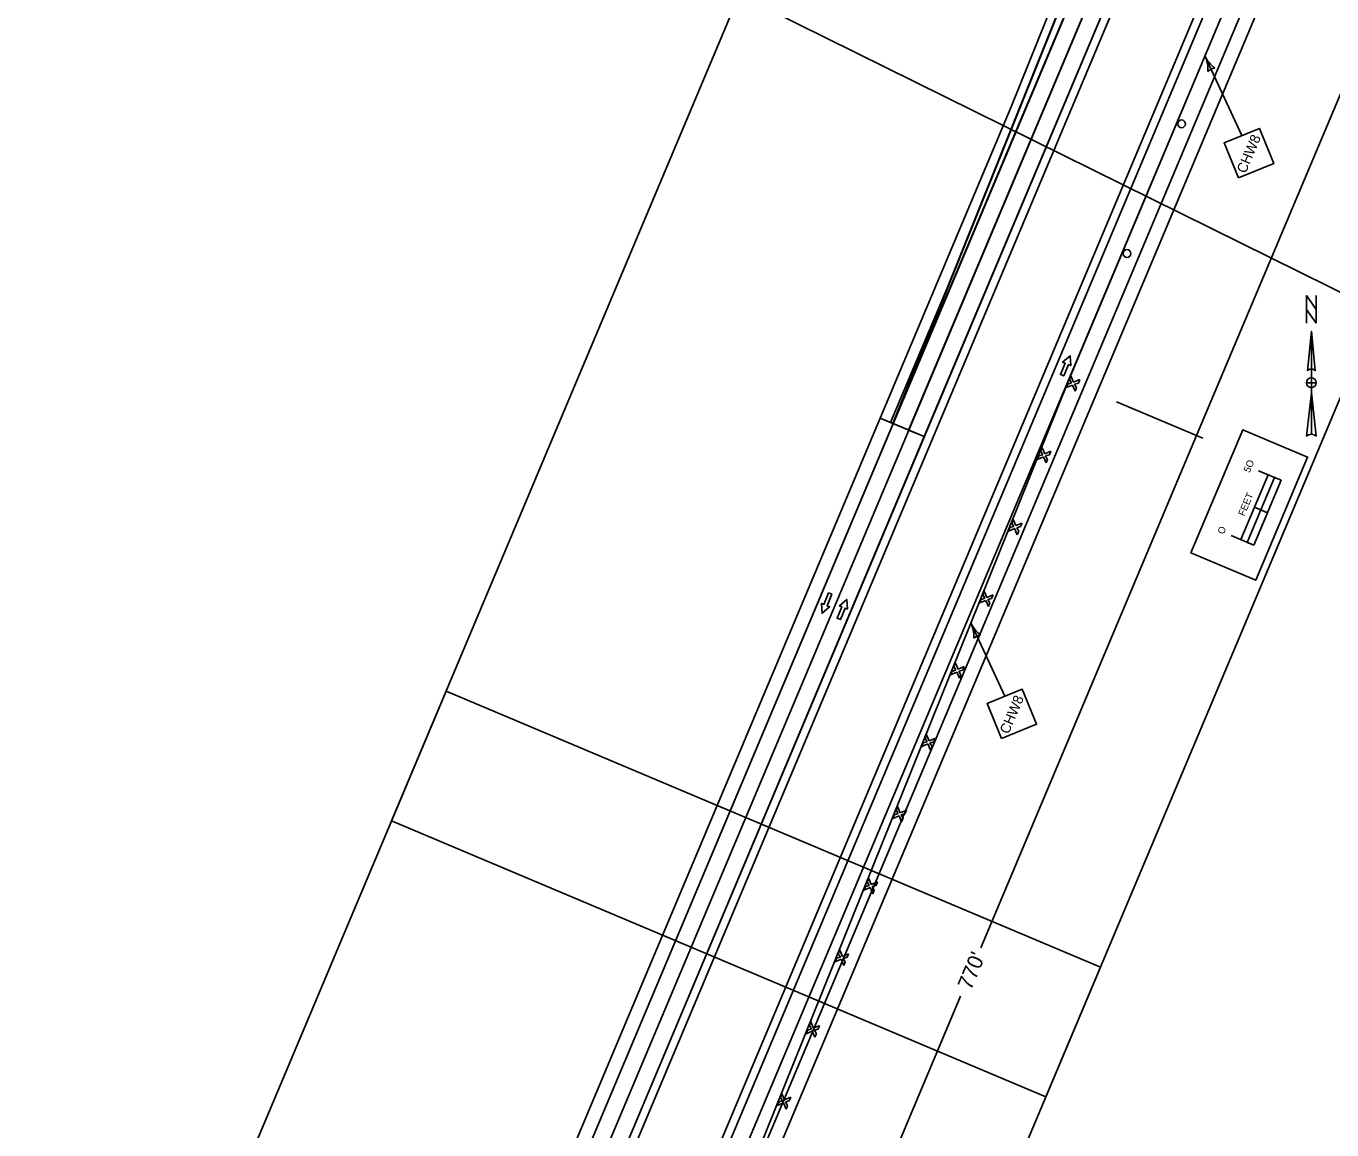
# Model space of a CAD drawing. Extents: x 14104283 to 14129344, y 8637090 to 8673339.
# Drawn here: x 14117797 to 14118725, y 8666942 to 8667727 of the extents above; entities that cross this region are included whole.
import ezdxf

# ---------------------------------------------------------------- set-up
doc = ezdxf.new("R2010")
doc.units = 0
for name, color, linetype in [('Cell', 7, 'Continuous'), ('Default', 7, 'Continuous'), ('dsnCellsNorthArrow', 7, 'Continuous'), ('dsnCellsScaleBlock', 7, 'Continuous'), ('dsnNonPlotable', 7, 'Continuous'), ('dsnPaintExistingBrokenLaneLineWhite', 7, 'Continuous'), ('dsnPaintExistingEdgeLineLeftYellow', 7, 'Continuous'), ('dsnPaintExistingEdgeLineRightWhite', 7, 'Continuous'), ('dsnPaintPlaceChannelizingLaneWhite', 7, 'Continuous'), ('dsnShadingPaved', 7, 'Continuous'), ('dsnStdLabel', 7, 'Continuous'), ('dsnStgShadingPrevPav', 7, 'Continuous'), ('dsnTapePlaceChannelizingLaneWhite', 7, 'Continuous')]:
    doc.layers.add(name, color=color, linetype=linetype)

msp = doc.modelspace()

# ---------------------------------------------------------------- linework, layer by layer
at = {"layer": 'Cell'}
for p, q in [((14118539.73, 8667478.12), (14118538.71, 8667475.57)), ((14118541.6, 8667473.73), (14118539.73, 8667478.12)), ((14118537.4, 8667472.32), (14118536.37, 8667469.77)), ((14118536.37, 8667469.77), (14118540.76, 8667471.64)), ((14118540.14, 8667473.1), (14118537.4, 8667472.32)), ((14118538.71, 8667475.57), (14118540.14, 8667473.1)), ((14118540.76, 8667471.64), (14118542.63, 8667467.25)), ((14118545.99, 8667475.6), (14118541.6, 8667473.73)), ((14118542.23, 8667472.26), (14118544.97, 8667473.04)), ((14118543.66, 8667469.8), (14118542.23, 8667472.26)), ((14118542.63, 8667467.25), (14118543.66, 8667469.8)), ((14118544.97, 8667473.04), (14118545.99, 8667475.6)), ((14118516.84, 8667421.31), (14118515.82, 8667418.75)), ((14118519.59, 8667422.09), (14118516.84, 8667421.31)), ((14118519.18, 8667427.1), (14118518.15, 8667424.55)), ((14118518.15, 8667424.55), (14118519.59, 8667422.09)), ((14118521.05, 8667422.71), (14118519.18, 8667427.1)), ((14118525.44, 8667424.58), (14118521.05, 8667422.71)), ((14118521.67, 8667421.25), (14118524.41, 8667422.03)), ((14118523.11, 8667418.78), (14118521.67, 8667421.25)), ((14118524.41, 8667422.03), (14118525.44, 8667424.58)), ((14118515.82, 8667418.75), (14118520.21, 8667420.62)), ((14118520.21, 8667420.62), (14118522.08, 8667416.23)), ((14118522.08, 8667416.23), (14118523.11, 8667418.78)), ((14118498.63, 8667376.09), (14118497.6, 8667373.54)), ((14118500.5, 8667371.7), (14118498.63, 8667376.09)), ((14118496.29, 8667370.29), (14118495.26, 8667367.74)), ((14118495.26, 8667367.74), (14118499.66, 8667369.61)), ((14118499.03, 8667371.07), (14118496.29, 8667370.29)), ((14118497.6, 8667373.54), (14118499.03, 8667371.07)), ((14118499.66, 8667369.61), (14118501.52, 8667365.22)), ((14118504.89, 8667373.56), (14118500.5, 8667371.7)), ((14118501.12, 8667370.23), (14118503.86, 8667371.01)), ((14118502.55, 8667367.77), (14118501.12, 8667370.23)), ((14118501.52, 8667365.22), (14118502.55, 8667367.77)), ((14118503.86, 8667371.01), (14118504.89, 8667373.56)), ((14118475.74, 8667319.27), (14118474.71, 8667316.72)), ((14118478.48, 8667320.06), (14118475.74, 8667319.27)), ((14118478.07, 8667325.07), (14118477.05, 8667322.52)), ((14118477.05, 8667322.52), (14118478.48, 8667320.06)), ((14118479.94, 8667320.68), (14118478.07, 8667325.07)), ((14118484.33, 8667322.55), (14118479.94, 8667320.68)), ((14118480.57, 8667319.22), (14118483.31, 8667320)), ((14118482, 8667316.75), (14118480.57, 8667319.22)), ((14118483.31, 8667320), (14118484.33, 8667322.55)), ((14118474.71, 8667316.72), (14118479.1, 8667318.59)), ((14118479.1, 8667318.59), (14118480.97, 8667314.2)), ((14118480.97, 8667314.2), (14118482, 8667316.75)), ((14118457.52, 8667274.06), (14118456.49, 8667271.51)), ((14118459.39, 8667269.66), (14118457.52, 8667274.06)), ((14118455.18, 8667268.26), (14118454.16, 8667265.71)), ((14118454.16, 8667265.71), (14118458.55, 8667267.58)), ((14118457.93, 8667269.04), (14118455.18, 8667268.26)), ((14118456.49, 8667271.51), (14118457.93, 8667269.04)), ((14118458.55, 8667267.58), (14118460.42, 8667263.19)), ((14118463.78, 8667271.53), (14118459.39, 8667269.66)), ((14118460.01, 8667268.2), (14118462.75, 8667268.98)), ((14118461.45, 8667265.74), (14118460.01, 8667268.2)), ((14118460.42, 8667263.19), (14118461.45, 8667265.74)), ((14118462.75, 8667268.98), (14118463.78, 8667271.53)), ((14118434.63, 8667217.24), (14118433.6, 8667214.69)), ((14118433.6, 8667214.69), (14118437.99, 8667216.56)), ((14118437.37, 8667218.03), (14118434.63, 8667217.24)), ((14118436.97, 8667223.04), (14118435.94, 8667220.49)), ((14118435.94, 8667220.49), (14118437.37, 8667218.03)), ((14118438.84, 8667218.65), (14118436.97, 8667223.04)), ((14118437.99, 8667216.56), (14118439.86, 8667212.17)), ((14118443.23, 8667220.52), (14118438.84, 8667218.65)), ((14118439.46, 8667217.19), (14118442.2, 8667217.97)), ((14118440.89, 8667214.72), (14118439.46, 8667217.19)), ((14118442.2, 8667217.97), (14118443.23, 8667220.52)), ((14118439.86, 8667212.17), (14118440.89, 8667214.72)), ((14118416.41, 8667172.03), (14118415.39, 8667169.48)), ((14118418.28, 8667167.63), (14118416.41, 8667172.03)), ((14118414.08, 8667166.23), (14118413.05, 8667163.68)), ((14118413.05, 8667163.68), (14118417.44, 8667165.55)), ((14118416.82, 8667167.01), (14118414.08, 8667166.23)), ((14118415.39, 8667169.48), (14118416.82, 8667167.01)), ((14118417.44, 8667165.55), (14118419.31, 8667161.16)), ((14118422.67, 8667169.5), (14118418.28, 8667167.63)), ((14118418.91, 8667166.17), (14118421.65, 8667166.95)), ((14118420.34, 8667163.71), (14118418.91, 8667166.17)), ((14118419.31, 8667161.16), (14118420.34, 8667163.71)), ((14118421.65, 8667166.95), (14118422.67, 8667169.5)), ((14118393.52, 8667115.21), (14118392.5, 8667112.66)), ((14118392.5, 8667112.66), (14118396.89, 8667114.53)), ((14118396.27, 8667116), (14118393.52, 8667115.21)), ((14118395.86, 8667121.01), (14118394.83, 8667118.46)), ((14118394.83, 8667118.46), (14118396.27, 8667116)), ((14118397.73, 8667116.62), (14118395.86, 8667121.01)), ((14118396.89, 8667114.53), (14118398.76, 8667110.14)), ((14118402.12, 8667118.49), (14118397.73, 8667116.62)), ((14118398.35, 8667115.16), (14118401.09, 8667115.94)), ((14118399.79, 8667112.69), (14118398.35, 8667115.16)), ((14118401.09, 8667115.94), (14118402.12, 8667118.49)), ((14118398.76, 8667110.14), (14118399.79, 8667112.69)), ((14118375.31, 8667070), (14118374.28, 8667067.44)), ((14118377.18, 8667065.6), (14118375.31, 8667070)), ((14118372.97, 8667064.2), (14118371.94, 8667061.65)), ((14118371.94, 8667061.65), (14118376.33, 8667063.52)), ((14118375.71, 8667064.98), (14118372.97, 8667064.2)), ((14118374.28, 8667067.44), (14118375.71, 8667064.98)), ((14118376.33, 8667063.52), (14118378.2, 8667059.13)), ((14118381.57, 8667067.47), (14118377.18, 8667065.6)), ((14118377.8, 8667064.14), (14118380.54, 8667064.92)), ((14118379.23, 8667061.68), (14118377.8, 8667064.14)), ((14118378.2, 8667059.13), (14118379.23, 8667061.68)), ((14118380.54, 8667064.92), (14118381.57, 8667067.47)), ((14118352.42, 8667013.18), (14118351.39, 8667010.63)), ((14118351.39, 8667010.63), (14118355.78, 8667012.5)), ((14118355.16, 8667013.97), (14118352.42, 8667013.18)), ((14118354.75, 8667018.98), (14118353.73, 8667016.43)), ((14118353.73, 8667016.43), (14118355.16, 8667013.97)), ((14118356.62, 8667014.59), (14118354.75, 8667018.98)), ((14118355.78, 8667012.5), (14118357.65, 8667008.11)), ((14118361.01, 8667016.46), (14118356.62, 8667014.59)), ((14118357.25, 8667013.12), (14118359.99, 8667013.91)), ((14118358.68, 8667010.66), (14118357.25, 8667013.12)), ((14118359.99, 8667013.91), (14118361.01, 8667016.46)), ((14118357.65, 8667008.11), (14118358.68, 8667010.66)), ((14118334.2, 8666967.96), (14118333.17, 8666965.41)), ((14118336.07, 8666963.57), (14118334.2, 8666967.96)), ((14118331.86, 8666962.17), (14118330.84, 8666959.62)), ((14118330.84, 8666959.62), (14118335.23, 8666961.49)), ((14118334.6, 8666962.95), (14118331.86, 8666962.17)), ((14118333.17, 8666965.41), (14118334.6, 8666962.95)), ((14118335.23, 8666961.49), (14118337.1, 8666957.09)), ((14118340.46, 8666965.44), (14118336.07, 8666963.57)), ((14118336.69, 8666962.11), (14118339.43, 8666962.89)), ((14118338.12, 8666959.65), (14118336.69, 8666962.11)), ((14118337.1, 8666957.09), (14118338.12, 8666959.65)), ((14118339.43, 8666962.89), (14118340.46, 8666965.44))]:
    msp.add_line(p, q, dxfattribs=at)
for points in [[(14118534.52, 8667478.07), (14118532.2, 8667479.01), (14118535.52, 8667487.11), (14118533.79, 8667487.82), (14118539.05, 8667492.42), (14118539.57, 8667485.45), (14118537.84, 8667486.16)], [(14118367.3, 8667323.84), (14118369.62, 8667322.89), (14118366.29, 8667314.79), (14118368.03, 8667314.08), (14118362.76, 8667309.49), (14118362.25, 8667316.45), (14118363.98, 8667315.74)], [(14118375.73, 8667304.96), (14118373.42, 8667305.91), (14118376.74, 8667314), (14118375, 8667314.71), (14118380.27, 8667319.31), (14118380.78, 8667312.34), (14118379.05, 8667313.05)]]:
    msp.add_lwpolyline(points, close=True, dxfattribs=at)
for points in [[(14118537.84, 8667486.16), (14118539.57, 8667485.45), (14118539.05, 8667492.42), (14118533.79, 8667487.82), (14118535.52, 8667487.11), (14118532.2, 8667479.01), (14118534.52, 8667478.07), (14118537.84, 8667486.16)], [(14118363.98, 8667315.74), (14118362.25, 8667316.45), (14118362.76, 8667309.49), (14118368.03, 8667314.08), (14118366.29, 8667314.79), (14118369.62, 8667322.89), (14118367.3, 8667323.84), (14118363.98, 8667315.74)], [(14118379.05, 8667313.05), (14118380.78, 8667312.34), (14118380.27, 8667319.31), (14118375, 8667314.71), (14118376.74, 8667314), (14118373.42, 8667305.91), (14118375.73, 8667304.96), (14118379.05, 8667313.05)]]:
    msp.add_lwpolyline(points, dxfattribs=at)
for centre in [(14118618.36, 8667657.23), (14118579.53, 8667565.07)]:
    msp.add_circle(centre, 2.75, dxfattribs=at)
at = {"layer": 'Default'}
msp.add_line((14118435.37, 8667434.94), (14118413.25, 8667444.25), dxfattribs=at)
for points in [[(14118413.25, 8667444.25), (14110818.39, 8649409.15), (14109142.61, 8645431.44)], [(14109164.73, 8645422.12), (14110840.51, 8649399.84), (14118435.37, 8667434.94)]]:
    msp.add_lwpolyline(points, dxfattribs=at)
at = {"layer": 'dsnCellsNorthArrow'}
for p, q in [((14118710.66, 8667509.85), (14118713.47, 8667481.68)), ((14118710.66, 8667509.85), (14118710.66, 8667436.61)), ((14118707.84, 8667481.68), (14118707.84, 8667481.68)), ((14118707.95, 8667481.94), (14118708.47, 8667482.53)), ((14118710.66, 8667469.71), (14118710.66, 8667469.71)), ((14118707.14, 8667435.2), (14118710.66, 8667466.19))]:
    msp.add_line(p, q, dxfattribs=at)
msp.add_lwpolyline([(14118714.18, 8667515.49), (14118707.14, 8667525.35), (14118707.14, 8667535.21), (14118714.18, 8667525.35)], close=True, dxfattribs=at)
for points in [[(14118707.14, 8667515.49), (14118707.14, 8667535.21), (14118714.18, 8667525.35), (14118714.18, 8667535.21)], [(14118707.84, 8667481.68), (14118710.66, 8667509.85), (14118710.66, 8667483.09)], [(14118714.18, 8667473.23), (14118710.66, 8667473.23), (14118710.66, 8667476.75)], [(14118710.66, 8667469.71), (14118710.66, 8667473.23), (14118707.14, 8667473.23)], [(14118710.66, 8667436.61), (14118710.66, 8667466.19), (14118714.18, 8667435.2)]]:
    msp.add_lwpolyline(points, dxfattribs=at)
for centre, radius, start, end in [((14118710.66, 8667473.23), 3.52, 90, 180), ((14118710.66, 8667479.57), 3.52, 90.02039, 143.12574), ((14118710.66, 8667479.57), 3.52, 36.84806, 90.02184), ((14118710.66, 8667473.23), 3.52, 0, 90), ((14118710.66, 8667473.23), 3.52, 180, 270), ((14118710.66, 8667473.23), 3.52, 270, 360), ((14118710.66, 8667431.51), 5.1, 89.98939, 133.61895), ((14118710.66, 8667431.5), 5.11, 46.40206, 90.00064)]:
    msp.add_arc(centre, radius, start, end, dxfattribs=at)
at = {"layer": 'dsnCellsScaleBlock'}
msp.add_line((14118679.37, 8667380.9), (14118670.15, 8667384.78), dxfattribs=at)
msp.add_line((14118679.37, 8667380.9), (14118670.15, 8667384.78), dxfattribs=at)
for points in [[(14118671.06, 8667332.86), (14118624.98, 8667352.27), (14118661.87, 8667439.82), (14118707.94, 8667420.4)], [(14118624.98, 8667352.27), (14118661.87, 8667439.82), (14118707.94, 8667420.4), (14118671.06, 8667332.86)], [(14118671.06, 8667332.86), (14118624.98, 8667352.27), (14118661.87, 8667439.82), (14118707.94, 8667420.4)], [(14118674.73, 8667382.85), (14118684.43, 8667405.89), (14118679.86, 8667407.82), (14118670.15, 8667384.78)], [(14118669.66, 8667357.86), (14118679.37, 8667380.9), (14118674.73, 8667382.85), (14118665.02, 8667359.82)]]:
    msp.add_lwpolyline(points, close=True, dxfattribs=at)
for points in [[(14118653.53, 8667364.66), (14118669.66, 8667357.86), (14118689.07, 8667403.94), (14118672.95, 8667410.73)], [(14118660.44, 8667361.74), (14118679.86, 8667407.82)]]:
    msp.add_lwpolyline(points, dxfattribs=at)
at = {"layer": 'dsnNonPlotable'}
for points in [[(14118092.03, 8667853.71), (14118786.76, 8669258.84), (14119692.14, 8668811.2), (14118997.41, 8667406.07)], [(14118056.48, 8667161.91), (14118665.06, 8668606.45), (14119130.44, 8668410.38), (14118521.87, 8666965.84)], [(14117486.73, 8665809.52), (14118095.31, 8667254.06), (14118560.69, 8667058), (14117952.12, 8665613.46)]]:
    msp.add_lwpolyline(points, close=True, dxfattribs=at)
at = {"layer": 'dsnPaintExistingBrokenLaneLineWhite'}
for p, q in [((14114932.53, 8658913.38), (14118863.73, 8668248.6)), ((14118664.08, 8668008.96), (14118424.31, 8667439.59)), ((14110829.45, 8649404.5), (14118424.31, 8667439.59))]:
    msp.add_line(p, q, dxfattribs=at)
at = {"layer": 'dsnPaintExistingEdgeLineLeftYellow'}
for p, q in [((14115900.95, 8661243.95), (14118759.37, 8668031.7)), ((14118675.14, 8668004.3), (14118435.37, 8667434.94)), ((14118435.37, 8667434.94), (14115816.14, 8661215.2)), ((14118435.37, 8667434.94), (14115816.14, 8661215.2))]:
    msp.add_line(p, q, dxfattribs=at)
at = {"layer": 'dsnPaintExistingEdgeLineRightWhite'}
for p, q in [((14110924.38, 8649364.51), (14118874.68, 8668243.67)), ((14118643.53, 8668017.62), (14118412.94, 8667444.38)), ((14118413.25, 8667444.25), (14115798.75, 8661235.75))]:
    msp.add_line(p, q, dxfattribs=at)
at = {"layer": 'dsnPaintPlaceChannelizingLaneWhite'}
msp.add_line((14118766.99, 8668018.87), (14118537.63, 8667474.22), dxfattribs=at)
at = {"layer": 'dsnShadingPaved'}
for p, q in [((14118227.72, 8666769.23), (14118759.37, 8668031.7)), ((14118770.49, 8668027.18), (14118537.63, 8667474.22)), ((14118534.18, 8667731.73), (14118412.93, 8667443.47)), ((14118412.93, 8667443.47), (14118528.39, 8667730.93)), ((14118537.63, 8667474.22), (14118249.84, 8666759.92))]:
    msp.add_line(p, q, dxfattribs=at)
for points in [[(14118653.02, 8668013.62), (14118412.94, 8667444.38), (14118424.31, 8667439.59), (14118664.08, 8668008.96)], [(14118435.37, 8667434.94), (14118675.14, 8668004.3), (14118664.08, 8668008.96), (14118424.15, 8667439.66)]]:
    msp.add_lwpolyline(points, close=True, dxfattribs=at)
at = {"layer": 'dsnStdLabel'}
for p, q in [((14118661.18, 8667648.87), (14118635.01, 8667705.48)), ((14118738.7, 8667695.95), (14118629.06, 8667435.71)), ((14118633.49, 8667433.84), (14118572.19, 8667459.66)), ((14118629.06, 8667435.71), (14118475.65, 8667071.56)), ((14118492.61, 8667250.42), (14118468.49, 8667302.61)), ((14118461.19, 8667037.24), (14118330.11, 8666726.11))]:
    msp.add_line(p, q, dxfattribs=at)
for points in [[(14118658.86, 8667618.77), (14118683.86, 8667628.95), (14118673.68, 8667653.96), (14118648.67, 8667643.78)], [(14118490.29, 8667220.32), (14118515.3, 8667230.5), (14118505.11, 8667255.51), (14118480.11, 8667245.32)]]:
    msp.add_lwpolyline(points, close=True, dxfattribs=at)
for centre, radius, start, end in [((14118614.18, 8667695.85), 22.95, 356.73394, 24.80525), ((14118655.85, 8667715.11), 22.95, 204.8051, 232.87636), ((14118643.09, 8667688.01), 8.86, 97.07093, 132.53937), ((14118447.66, 8667292.98), 22.95, 356.73394, 24.80525), ((14118489.32, 8667312.24), 22.95, 204.8051, 232.87636), ((14118476.56, 8667285.14), 8.86, 97.07093, 132.53937)]:
    msp.add_arc(centre, radius, start, end, dxfattribs=at)
at = {"layer": 'dsnStgShadingPrevPav'}
for p, q in [((14115895.65, 8661246.83), (14118811.53, 8668171.01)), ((14118848.39, 8668155.49), (14115932.51, 8661231.3)), ((14118457.98, 8667555.62), (14118643.53, 8668017.62)), ((14118457.98, 8667555.62), (14118643.53, 8668017.62)), ((14118637.96, 8668019.85), (14118497.16, 8667669.27)), ((14118653.02, 8668013.62), (14115794.02, 8661224.52)), ((14118652.65, 8668013.06), (14118415.89, 8667450.85)), ((14115816.14, 8661215.2), (14118675.14, 8668004.3)), ((14115816.14, 8661215.2), (14118675.14, 8668004.3)), ((14118680.66, 8668001.98), (14115821.67, 8661212.88)), ((14118497.16, 8667669.27), (14118404.03, 8667448.13)), ((14118411.4, 8667445.03), (14118457.98, 8667555.62)), ((14118411.4, 8667445.03), (14118457.98, 8667555.62)), ((14118415.89, 8667450.85), (14118413.13, 8667444.3)), ((14110809.18, 8649413.03), (14118404.03, 8667448.13)), ((14118413.25, 8667444.25), (14110818.39, 8649409.15)), ((14118404.03, 8667448.13), (14118411.4, 8667445.03)), ((14118404.03, 8667448.13), (14118413.25, 8667444.25)), ((14118413.25, 8667444.25), (14118411.4, 8667445.03))]:
    msp.add_line(p, q, dxfattribs=at)
at = {"layer": 'dsnTapePlaceChannelizingLaneWhite'}
msp.add_line((14118249.84, 8666759.92), (14118537.63, 8667474.22), dxfattribs=at)

# ---------------------------------------------------------------- texts
at = {"layer": 'dsnCellsScaleBlock'}
for s, p in [('5O', (14118666.75, 8667408.92)), ('FEET', (14118662.98, 8667378.06)), ('O', (14118648.29, 8667365.09))]:
    msp.add_text(s, height=5, rotation=67.1547, dxfattribs=at).set_placement(p)
at = {"layer": 'dsnStdLabel'}
for s, height, p in [('CHW8', 7.2, (14118663.92, 8667621.53)), ('CHW8', 7.2, (14118495.36, 8667223.07)), ("770'", 10.8, (14118468.63, 8667041))]:
    msp.add_text(s, height=height, rotation=67.1547, dxfattribs=at).set_placement(p)

doc.saveas('drawing.dxf')
